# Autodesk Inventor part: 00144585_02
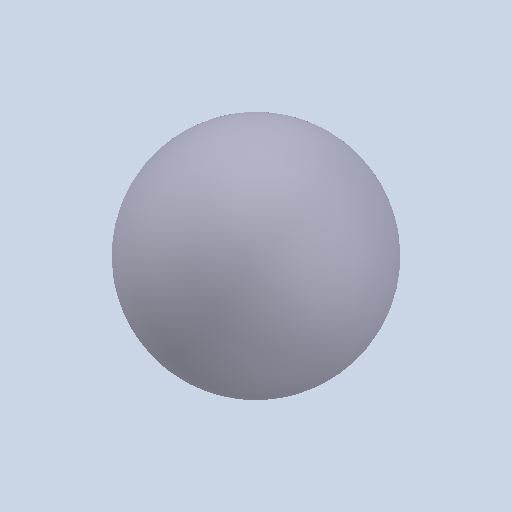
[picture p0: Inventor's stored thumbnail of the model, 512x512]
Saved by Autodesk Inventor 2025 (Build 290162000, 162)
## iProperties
Created: 2021-02
Part Number: 00144585_02
Material: Generico
Document SubType Name: Modeling
Designer: Ryzen5700u
Density: 1 g/cm^3
Appearance: Default
Author: Ryzen5700u
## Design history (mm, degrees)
feature "Solido1"
node "Solido2"
